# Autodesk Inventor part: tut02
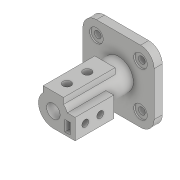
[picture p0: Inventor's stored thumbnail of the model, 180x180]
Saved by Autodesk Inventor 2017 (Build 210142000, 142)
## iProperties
Created: 2015-03
Part Number: tut02
Material: Generic
Document SubType Name: Modeling
Designer: Sandeep
Density: 1 g/cm^3
Appearance: Default
Author: Sandeep
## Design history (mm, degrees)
sketch "Sketch1"
  geometry: L1 (-32.5, -52.5)-(32.5, -52.5); L2 (52.5, -32.5)-(52.5, 32.5); L3 (32.5, 52.5)-(-32.5, 52.5); L4 (-52.5, 32.5)-(-52.5, -32.5); L5 (-52.5, -52.5)-(52.5, 52.5); L6 (52.5, -52.5)-(-52.5, 52.5); A1 r 20 centre (32.5, 32.5) between (52.5, 32.5) and (32.5, 52.5); A2 r 20 centre (32.5, -32.5) between (32.5, -52.5) and (52.5, -32.5); A3 r 20 centre (-32.5, -32.5) between (-52.5, -32.5) and (-32.5, -52.5); A4 r 20 centre (-32.5, 32.5) between (-32.5, 52.5) and (-52.5, 32.5); 1 further point
  constraints: 12 end point, 8 point on circle, 8 point on line, 8 tangent, 4 centre point, 2 equal radius, 2 midpoint, 2 parallel, 1 horizontal, 1 perpendicular
  dimensions: "d0" = 105 distance of L6.start L5.end; "d1" = 105 distance of L5.start L6.start; "d2" = 20 radius of A1; "d3" = 20 radius of A2
extrude "Extrusion1" new body sketch "Sketch1" distance "d4" = 12; taper "d5" = 0 deg
hole "Hole1" diameter "d8" = 10; stored, may be unused: countersink angle "d12" = 90 deg, drill point angle "d14" = 118 deg; dims "d9" = 6, "d10" = 20, "d11" = 2, "d13" = 8, "d15" = 10, "d16" = 10
hole "Hole2" diameter "d19" = 10; stored, may be unused: countersink angle "d23" = 90 deg, drill point angle "d25" = 118 deg; dims "d17" = 10, "d18" = 10, "d20" = 6, "d21" = 20, "d22" = 2, "d24" = 8
hole "Hole3" diameter "d28" = 10; stored, may be unused: countersink angle "d32" = 90 deg, drill point angle "d34" = 118 deg; dims "d26" = 10, "d27" = 10, "d29" = 6, "d30" = 20, "d31" = 2, "d33" = 8
hole "Hole4" diameter "d37" = 10; stored, may be unused: countersink angle "d41" = 90 deg, drill point angle "d43" = 118 deg; dims "d35" = 10, "d36" = 10, "d38" = 6, "d39" = 20, "d40" = 2, "d42" = 8
sketch "Sketch2"
  geometry: C1 r 22 at (0, 0); 1 further point
  constraints: 1 centre point, 1 coincident
  dimensions: "d44" = 44 diameter of C1
extrude "Extrusion2" join sketch "Sketch2" distance "d45" = 96; taper "d46" = 0 deg
sketch "Sketch3"
  geometry: L1 (-15, 16.093)-(-15, 25); L2 (15, 16.093)-(15, 25); L3 (-15, 25)-(15, 25); L4 (0, 0)-(20.619, 0); L5 (0, 6.043)-(0, 0); A1 r 22 centre (0, 0) between (15, 16.093) and (-15, 16.093); 1 further point
  constraints: 10 end point, 3 vertical, 2 horizontal, 2 point on circle, 1 centre point, 4 other
  dimensions: "d48" = 25 distance from line of point (0, 0) L3; "d49" = 30 distance of L1.end L2.end
extrude "Extrusion3" join sketch "Sketch3" distance "d51" = 76; taper "d52" = 0 deg
sketch "Sketch4"
  geometry: L1 (20.494, 8)-(32, 8); L2 (32, 8)-(32, -22); L3 (0, 0)-(37.067, 0); L4 (0, -22)-(32, -22); A1 r 22 centre (0, 0) between (20.494, 8) and (0, -22) reference; A2 r 22 centre (0, 0) between (0, -22) and (20.494, 8); 1 further point
  constraints: 8 end point, 5 point on circle, 2 horizontal, 2 perpendicular, 1 centre point, 1 concentric, 1 tangent
  dimensions: "d53" = 30 distance of L2.end L1.end; "d54" = 32 distance from line of L2 point (0, 0)
extrude "Extrusion4" join sketch "Sketch4" distance "d55" = 57; taper "d56" = 0 deg
sketch "Sketch5"
  geometry: L1 (17, -2)-(25, -2); L2 (25, -2)-(25, -18); L3 (25, -18)-(17, -18); L4 (17, -18)-(17, -2); 1 further point
  constraints: 8 end point, 2 parallel, 1 horizontal, 1 perpendicular
  dimensions: "d57" = 16 distance of L1.end L2.end; "d58" = 2 distance from line of point (0, 0) L1; "d59" = 25 distance from line of point (0, 0) L2; "d60" = 8 distance of L2.end L3.end
extrude "Extrusion5" cut sketch "Sketch5" distance "d61" = 50; taper "d62" = 0 deg
hole "Hole6" diameter "d77" = 20; stored, may be unused: countersink angle "d81" = 90 deg, drill point angle "d83" = 118 deg; dims "d75" = 10, "d76" = 10, "d78" = 6, "d79" = 4, "d80" = 2, "d82" = 96
hole "Hole7" diameter "d86" = 12; stored, may be unused: countersink angle "d90" = 90 deg, drill point angle "d92" = 118 deg; dims "d84" = 20, "d85" = 15, "d87" = 6, "d88" = 4, "d89" = 2, "d91" = 96
hole "Hole8" diameter "d95" = 12; stored, may be unused: countersink angle "d99" = 90 deg, drill point angle "d101" = 118 deg; dims "d93" = 50, "d94" = 15, "d96" = 6, "d97" = 4, "d98" = 2, "d100" = 96
hole "Hole10" diameter "d113" = 10; stored, may be unused: countersink angle "d117" = 90 deg, drill point angle "d119" = 118 deg; dims "d111" = 15, "d112" = 15, "d114" = 6, "d115" = 4, "d116" = 2, "d118" = 96
hole "Hole11" diameter "d122" = 10; stored, may be unused: countersink angle "d126" = 90 deg, drill point angle "d128" = 118 deg; dims "d120" = 37, "d121" = 15, "d123" = 6, "d124" = 4, "d125" = 2, "d127" = 96
body "Solid1"
